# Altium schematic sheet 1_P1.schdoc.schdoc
size 309 x 223 mm; Symbol: Sheet-Symbol_A4; Device: Sheet-Symbol_A4; Company: Sai Automations; Drawed: EasyEDA Pro; Reviewed: EasyEDA Pro; Version: V0.1; Page Size: A4; @Project Name: SHA-PCB V1.1; @Page Count: 2; @Update Date: 2024-07-24; @Create Date: 2023-12-23; @Schematic Name: Schematic1; Part Number: JLCPCB-002; @Page No: 1; @Page Name: P1
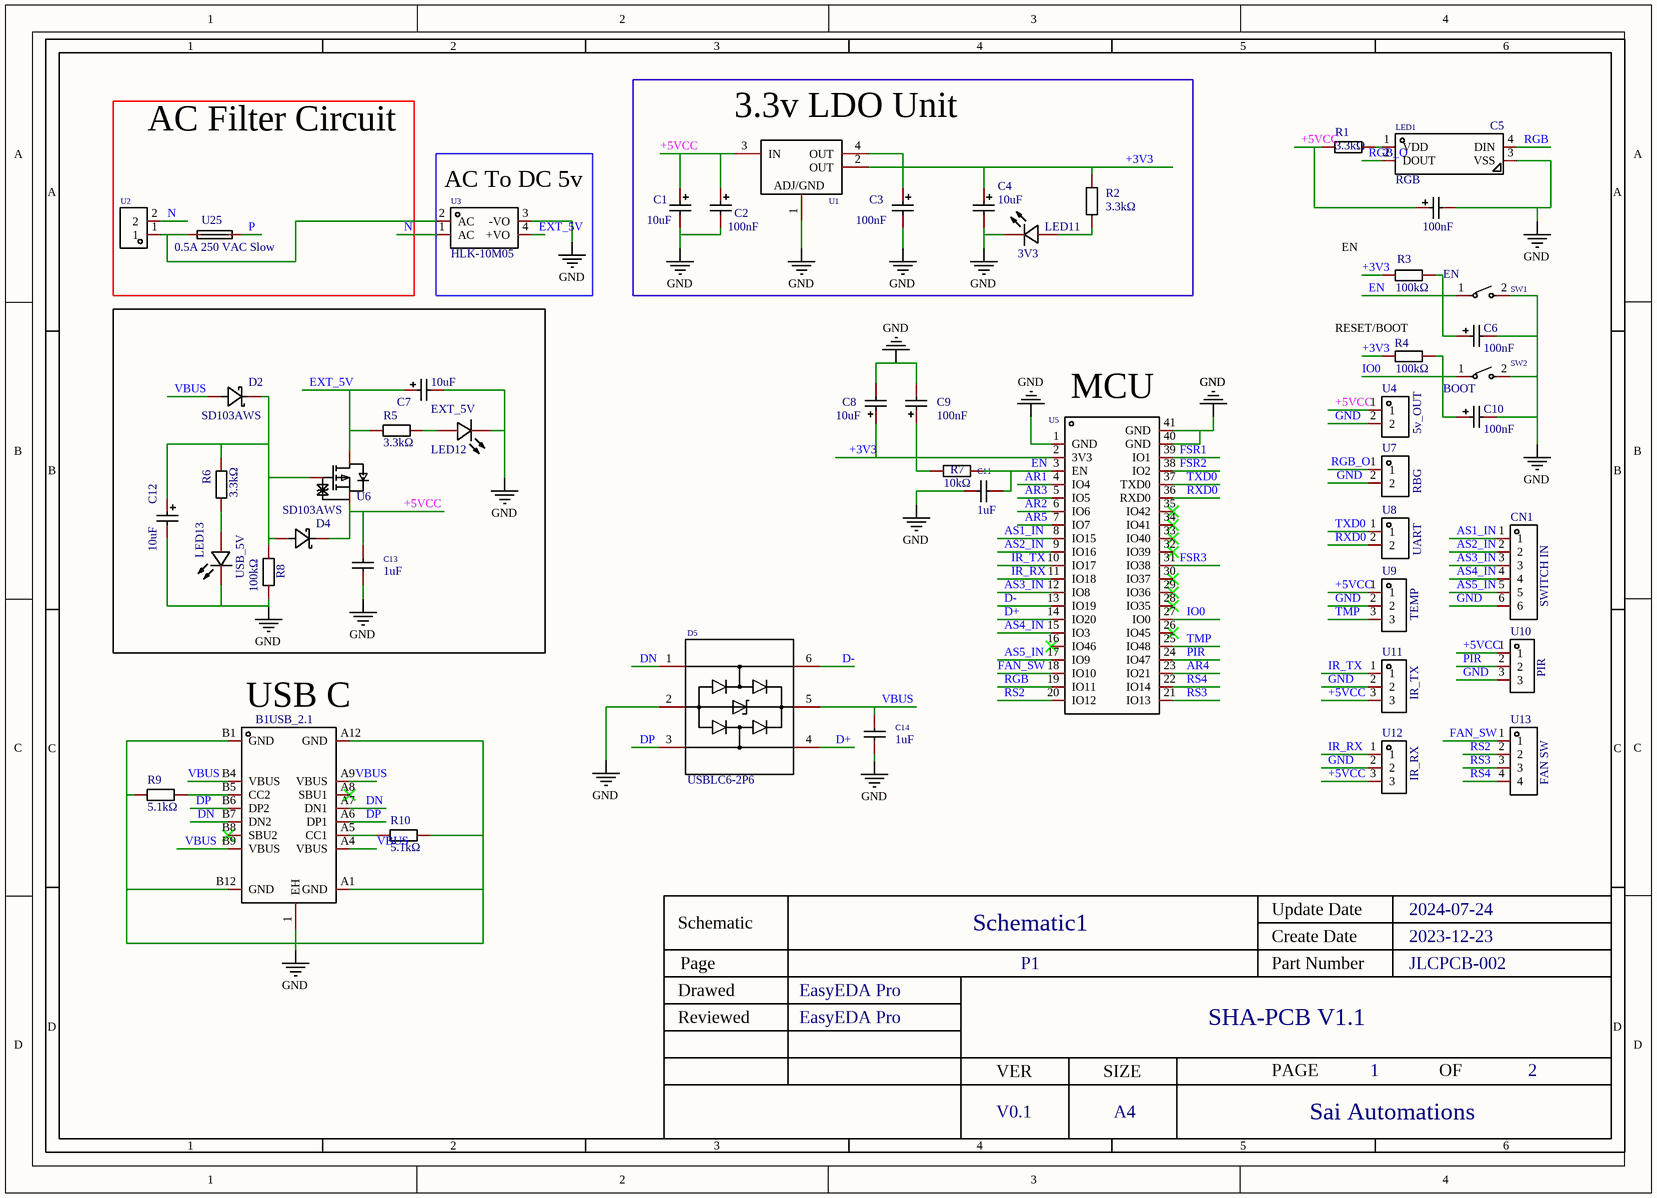
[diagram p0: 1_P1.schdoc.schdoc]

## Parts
B1  USB_2.1  [TYPE-C-SMD_SBC-160S1A-20-S412]
C1  10uF  [CASE-A_3216]
C2  100nF  [CASE-A_3216]
C3  100nF  [CASE-A_3216]
C4  10uF  [CASE-A_3216]
C5  100nF  [CASE-A_3216]
C6  100nF  [CASE-A_3216]
C7  10uF  [CASE-A_3216]
C8  10uF  [CASE-B_3528]
C9  100nF  [CASE-A_3216]
C10  100nF  [CASE-A_3216]
C11  1uF  [C0402]
C12  10uF  [CASE-A_3216]
C13  1uF  [C0402]
C14  1uF  [C0402]
CN1  SWITCH IN  [CONN-TH_B6B-PH-K-S-GW]
D2  SD103AWS  [SOD-323_L1.8-W1.3-LS2.5-FD]
D4  SD103AWS  [SOD-323_L1.8-W1.3-LS2.5-FD]
D5  USBLC6-2P6  [SOT-666-6_L1.6-W1.2-P0.50-LS1.6-BR]
LED1  RGB  [LED-SMD_4P-L5.0-W5.0-BL_TC5050RGB]
LED11  3V3  [LED0805-R-RD]
LED12  EXT_5V  [LED0805-R-RD]
LED13  USB_5V  [LED0805-R-RD]
R1  3.3kΩ  [R0402]
R2  3.3kΩ  [R0402]
R3  100kΩ  [R0402]
R4  100kΩ  [R0402]
R5  3.3kΩ  [R0402]
R6  3.3kΩ  [R0402]
R7  10kΩ  [R0402]
R8  100kΩ  [R0402]
R9  5.1kΩ  [R0402]
R10  5.1kΩ  [R0402]
SW1  EN  [SW-SMD_L3.9-W3.0-P4.45]
SW2  BOOT  [SW-SMD_L3.9-W3.0-P4.45]
U1  AMS1117-3.3  [SOT-223-3_L6.4-W3.5-P2.30-LS7.0-BR]  (value not drawn)
U2  XY126V-5.0-2P  [CONN-TH_XY126V-5.0-2P]  (value not drawn)
U3  HLK-10M05  [PWRM-TH_HLK-10M05]
U4  5v_OUT  [CONN-TH_2P-P2.00_2B-PH-KL]
U5  ESP32-S3-WROOM-1-N4R8  [WIRELM-SMD_ESP32-S3-WROOM-1]  (value not drawn)
U6  CJ3139KDW-ES  [SOT-323-3_L2.1-W1.3-P1.30-LS2.3-BR]  (value not drawn)
U7  RBG  [CONN-TH_2P-P2.00_2B-PH-KL]
U8  UART  [CONN-TH_2P-P2.00_2B-PH-KL]
U9  TEMP  [3 PIN JST PH]
U10  PIR  [3 PIN JST PH]
U11  IR_TX  [3 PIN JST PH]
U12  IR_RX  [3 PIN JST PH]
U13  FAN SW  [JST 4PIN]
U25  0.5A 250 VAC Slow  [TH_2P-BLX-A]

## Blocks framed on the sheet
3.3v LDO Unit: C1-C4 LED11 R2 U1
AC Filter Circuit: U2 U25
AC To DC 5v: U3

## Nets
GND: B1.1(EH) B1.A1(GND) B1.A12(GND) B1.B1(GND) B1.B12(GND) C1.2 C2.2 C3.2 C4.2 C5.2 C6.2 C7.2 C8.2 C9.2 C10.2 C11.2 C12.2 C13.2 C14.2 CN1.6 D5.2(GND) LED1.3(VSS) LED11.2(-) LED12.2(-) LED13.2(-) R8.1 R9.1 R10.2 SW1.2 SW2.2 U1.1(ADJ/GND) U3.3(-VO) U4.2 U5.1(GND) U5.40(GND) U5.41(GND) U7.2 U9.2 U10.3 U11.2 U12.2
+3V3: C3.1 C4.1 C8.1 C9.1 R2.2 R3.1 R4.2 R7.2 U1.2(OUT) U1.4(OUT) U5.2(3V3)
+5VCC: C1.1 C2.1 C5.1 C13.1 D4.2(K) R1.1 U1.3(IN) U4.1 U6.2(S) U9.1 U10.1 U11.3 U12.3
AR1: U5.4(IO4)
AR2: U5.6(IO6)
AR3: U5.5(IO5)
AR4: U5.23(IO21)
AR5: U5.7(IO7)
AS1_IN: CN1.1 U5.8(IO15)
AS2_IN: CN1.2 U5.9(IO16)
AS3_IN: CN1.3 U5.12(IO8)
AS4_IN: CN1.4 U5.15(IO3)
AS5_IN: CN1.5 U5.17(IO9)
D+: D5.4(I/O2) U5.14(IO20)
D-: D5.6(I/O1) U5.13(IO19)
DN: B1.A7(DN1) B1.B7(DN2) D5.1(I/O1)
DP: B1.A6(DP1) B1.B6(DP2) D5.3(I/O2)
EN: C6.1 C11.1 R3.2 R7.1 SW1.1 U5.3(EN)
EXT_5V: C7.1 R5.1 U3.4(+VO) U6.3(D)
FAN_SW: U5.18(IO10) U13.1
FSR1: U5.39(IO1)
FSR2: U5.38(IO2)
FSR3: U5.31(IO38)
IO0: C10.1 R4.1 SW2.1 U5.27(IO0)
IR_RX: U5.11(IO18) U12.1
IR_TX: U5.10(IO17) U11.1
N: U2.2 U3.1(AC)
P: U25.2
PIR: U5.24(IO47) U10.2
RGB: LED1.4(DIN) U5.19(IO11)
RGB_O: LED1.2(DOUT) U7.1
RS2: U5.20(IO12) U13.2
RS3: U5.21(IO13) U13.3
RS4: U5.22(IO14) U13.4
RXD0: U5.36(RXD0) U8.2
TMP: U5.25(IO48) U9.3
TXD0: U5.37(TXD0) U8.1
VBUS: B1.A4(VBUS) B1.A9(VBUS) B1.B4(VBUS) B1.B9(VBUS) C14.1 D2.1(A) D5.5(VBUS)
NetB1_A5: B1.A5(CC1) R10.1
NetB1_B5: B1.B5(CC2) R9.2
NetC12_1: C12.1 D2.2(K) D4.1(A) R6.1 R8.2 U6.1(G)
NetLED1_1: LED1.1(VDD) R1.2
NetLED11_1: LED11.1(+) R2.1
NetLED12_1: LED12.1(+) R5.2
NetLED13_1: LED13.1(+) R6.2
NetU2_1: U2.1 U3.2(AC) U25.1

Not connected (* = marked no-connect by the designer): B1 A8(SBU1)* B8(SBU2)*; U5 16(IO46)* 26(IO45)* 28(IO35)* 29(IO36)* 30(IO37)* 32(IO39)* 33(IO40)* 34(IO41)* 35(IO42)*

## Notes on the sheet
- (near R3) EN
- (near R4) RESET/BOOT
- (near U5) MCU
- (near B1) USB C

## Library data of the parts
B1 = USB4105-GF-A: Add into BOM: yes
C1 C4 C7 C12 = TAJA106K010RNJ: Manufacturer: Kyocera AVX; Add into BOM: yes; Tolerance: ±10%; Equivalent Series Resistance(ESR): 3Ω@100kHz; Description: Capacitance: Tolerance:±10% Tolerance:±10% Rated Voltage: Equivalent Series Resistance(ESR):3Ω@100kHz Operating Temperature:-55℃~+125℃ Operating Temperature:-55℃~+125℃
C2 C3 C5 C6 C9 C10 = TAJA104K035RNJ: Manufacturer: Kyocera AVX; Add into BOM: yes; Tolerance: ±10%; Equivalent Series Resistance(ESR): 24Ω@100kHz; Description: Capacitance: Tolerance:±10% Tolerance:±10% Rated Voltage: Equivalent Series Resistance(ESR):24Ω@100kHz Operating Temperature:-55℃~+125℃ Operating Temperature:-55℃~+125℃
C8 = TAJB226K016RNJ: Manufacturer: Kyocera AVX; Add into BOM: yes; Tolerance: ±10%; Equivalent Series Resistance(ESR): 2.3Ω@100kHz; Description: Capacitance: Tolerance:±10% Tolerance:±10% Rated Voltage: Equivalent Series Resistance(ESR):2.3Ω@100kHz Operating Temperature:-55℃~+125℃ Operating Temperature:-55℃~+125℃
C11 C13 C14 = CL05A105KP5NNNC: Manufacturer: SAMSUNG(三星); Add into BOM: yes; Tolerance: ±10%; Description: Capacitance: Tolerance:±10% Tolerance:±10% Voltage Rated: Temperature Coefficient:
CN1 = B6B-PH-K-S-GW: Manufacturer: JST; Add into BOM: yes; Pins Structure: 1x6P; Pitch: 2mm; Reference Series: PH; Number of PINs Per Row: 6; Current Rating (Max): 2A; Rated Voltage (Max): 100V; Plastic Material: PA66; Flame Retardant Rating: UL94V-0; Supplementary Features: 打K脚; Z-Height of the Board: 6mm; X-Length of Bottom Edge on Board (Spacing Line): 13.9mm; Y-Width of Bottom Edge on Board: 4.5mm; Description: Pins Structure:1x6P Pitch:2mm Mounting Style:Straight Reference Series:PH Number of Pins:6P Number of Rows:1 Number of PINs Per Row:6 Row Spacing:- Current Rating (Max):2A Contact Material:Brass Contact Plating:Tin Operating Temperature Range:-25℃~+85℃ Op
D2 D4 = SD103AWS_C777800: Manufacturer: HT(金誉); Add into BOM: yes
D5 = USBLC6-2P6_C15999: Manufacturer: ST(意法半导体); Add into BOM: yes; polarity: Unidirectional; Reverse Stand-Off Voltage (Vrwm): 5.25V; Maximum Clamping Voltage: 17V; Peak Pulse Current (Ipp)@10/1000us: 5A; Breakdown Voltage: 6V; Number of Lines: Dual; Type: ESD; Description: polarity:Unidirectional Reverse Stand-Off Voltage (Vrwm):5.25V Maximum Clamping Voltage:17V Peak Pulse Current (Ipp)@10/1000us:5A Breakdown Voltage:6V Number of Lines:Dual Type:ESD
LED1 = WS2812B-B/W: Manufacturer: worldsemi; Add into BOM: yes; Description: Emitted Color:RGB
LED11-LED13 = KT-0805Y: Manufacturer: KENTO; Symbol: 17-21SUYC/TR8; Add into BOM: yes; Emitted Color: Yellow; Description: Emitted Color:Yellow Diode Configuration:- Forward Current:- Power Dissipation:- Lens Color:- Dominant Wavelength:- Dominant Wavelength:- Peak Wavelength:- Color Temperature:- Color Temperature:- Viewing Angle:- Mounting Sytle:- Operating Temperature:- Op
R1 R2 R5 R6 = RC0402FR-073K3L: Manufacturer: YAGEO(国巨); Add into BOM: yes; Tolerance: ±1%; Temperature Coefficient: ±100ppm/℃; Description: Type:Thick Film Resistors Resistance: Tolerance:±1% Tolerance:±1% Power(Watts): Overload Voltage (Max): Temperature Coefficient:±100ppm/℃ Temperature Coefficient:±100ppm/℃ Operating Temperature Range:-55℃~+155℃ Operating Temperature Range:-55℃~+155℃
R3 R4 R8 = RC0402FR-07100KL: Manufacturer: YAGEO(国巨); Add into BOM: yes; Tolerance: ±1%; Temperature Coefficient: ±100ppm/℃; Description: Type:Thick Film Resistors Resistance: Tolerance:±1% Tolerance:±1% Power(Watts): Overload Voltage (Max): Temperature Coefficient:±100ppm/℃ Temperature Coefficient:±100ppm/℃ Operating Temperature Range:-55℃~+155℃ Operating Temperature Range:-55℃~+155℃
R7 = RC0402FR-0710KL: Manufacturer: YAGEO(国巨); Add into BOM: yes; Tolerance: ±1%; Temperature Coefficient: ±100ppm/℃; Description: Type:Thick Film Resistors Resistance: Tolerance:±1% Tolerance:±1% Power(Watts): Temperature Coefficient:±100ppm/℃ Temperature Coefficient:±100ppm/℃ Overload Voltage (Max): Operating Temperature Range:-55℃~+155℃ Operating Temperature Range:-55℃~+155℃
R9 R10 = RC0402FR-075K1L: Manufacturer: YAGEO(国巨); Add into BOM: yes; Tolerance: ±1%; Temperature Coefficient: ±100ppm/℃; Description: Type:Thick Film Resistors Resistance: Tolerance:±1% Tolerance:±1% Power(Watts): Overload Voltage (Max): Temperature Coefficient:±100ppm/℃ Temperature Coefficient:±100ppm/℃ Operating Temperature Range:-55℃~+155℃ Operating Temperature Range:-55℃~+155℃
SW1 SW2 = TS-1088R-02526: Manufacturer: XUNPU(讯普); Add into BOM: yes; Circuit: SPST; Actuator Style: Round Button; Switch Length: 3.9mm; Switch Width: 2.93mm; Switch Height: 2.5mm; Contact Current: 50mA; Voltage Rating (DC): 12V; Description: Circuit:SPST Actuator Style:Round Button Mounting Style:Brick nogging Switch Length:3.9mm Switch Width:2.93mm Switch Height:2.5mm Contact Current:50mA Voltage Rating (DC):12V With Lamp:- Mechanical Life:-
U1 = AMS1117-3.3: Manufacturer: 国芯佳品; Symbol: AMS1117-3.3_C2992570; Add into BOM: yes
U2 = XY126V-5.0-2P: Manufacturer: XINLAIYA(新莱亚); Add into BOM: yes; Structure: 1x2P; Pitch: 5mm; Current Rating (Max): 10A; Voltage Rating (Max): 300V; Wire Gauge - AWG: 14~26; Wire Gauge - mm2: 2.5; Number of PINs Per Row: 2; Description: Structure:1x2P Pitch:5mm Color:Green Mounting Style:Straight Current Rating (Max):10A Voltage Rating (Max):300V Number of Pins:2P Number of Rows:1 Wire Gauge - AWG:14~26 Wire Gauge - AWG:14~26 Wire Gauge - mm2:2.5 Wire Gauge - mm2:2.5 Number of PINs Per R
U3 = HLK-10M05: Manufacturer: HI-LINK(海凌科); Add into BOM: yes; Conversion Type: AC-DC; Function: 降压型; Input Voltage(AC): 90VAC~265VAC; Input Voltage(DC): 120V~350V; Output Voltage: 5V; Output Current (Max): 2A; Output Power: 10W; Isolated Or Voltage Regulation: 隔离稳压; Output Channel: 1; Insulated Voltage: 3kV@AC; Conversion Efficiency: 80%; Description: Conversion Type:AC-DC Function:降压型 Input Voltage(AC):90VAC~265VAC Input Voltage(AC):90VAC~265VAC Input Voltage(DC):120V~350V Input Voltage(DC):120V~350V Output Voltage:5V Output Voltage:5V Output Current (Max):2A Output Current (Max):2A Output Power:10W I
U4 U7 U8 = B2B-PH-KL(LF)(SN): Manufacturer: JST; Add into BOM: yes; Pins Structure: 1x2P; Pitch: 2mm; Reference Series: PH; Number of PINs Per Row: 2; Current Rating (Max): 2A; Rated Voltage (Max): 100V; Plastic Material: PA66; Flame Retardant Rating: UL94V-0; Supplementary Features: 打K脚; Z-Height of the Board: 6mm; X-Length of Bottom Edge on Board (Spacing Line): 5.9mm; Y-Width of Bottom Edge on Board: 4.5mm; Description: Pins Structure:1x2P Pitch:2mm Mounting Style:Straight Reference Series:PH Number of Pins:2P Number of Rows:1 Number of PINs Per Row:2 Row Spacing:- Current Rating (Max):2A Contact Material:Copper Alloy Contact Plating:Tin Operating Temperature Range:-25℃~
U5 = ESP32-S3-WROOM-1-N4R8: Manufacturer: ESPRESSIF(乐鑫); Add into BOM: yes
U6 = CJ3139KDW-ES: Manufacturer: ElecSuper(静芯微); Add into BOM: yes; Continuous Drain Current (Id): 0.5A; Power Dissipation (Pd): 0.15W; Drain Source On Resistance (RDS(on)@Vgs,Id): 580mΩ; Gate Threshold Voltage (Vgs(th)@Id): 0.62V; Total Gate Charge (Qg@Vgs): 1.25nC; Input Capacitance (Ciss@Vds): 71pF; Reverse Transfer Capacitance (Crss@Vds): 15pF; Description: Drain Source Voltage (Vdss): Continuous Drain Current (Id):0.5A Power Dissipation (Pd):0.15W Drain Source On Resistance (RDS(on)@Vgs,Id):580mΩ Gate Threshold Voltage (Vgs(th)@Id):0.62V Total Gate Charge (Qg@Vgs):1.25nC Input Capacitance (Ciss@Vds):71pF Re
U9-U12 = B4B-PH-K-S-GW: Manufacturer: JST; Add into BOM: yes; Pins Structure: 1x4P; Pitch: 2mm; Reference Series: PH; Number of PINs Per Row: 4; Current Rating (Max): 2A; Rated Voltage (Max): 100V; Plastic Material: PA66; Flame Retardant Rating: UL94V-0; Supplementary Features: 打K脚; Z-Height of the Board: 6mm; X-Length of Bottom Edge on Board (Spacing Line): 9.9mm; Y-Width of Bottom Edge on Board: 4.5mm; Description: Pins Structure:1x4P Pitch:2mm Mounting Style:Straight Reference Series:PH Number of Pins:4P Number of Rows:1 Number of PINs Per Row:4 Row Spacing:- Current Rating (Max):2A Contact Material:Brass Contact Plating:Tin Operating Temperature Range:-25℃~+85℃ Op
U13 = B4B-PH-KL(LF)(SN): Manufacturer: JST; Add into BOM: yes; Pins Structure: 1x4P; Pitch: 2mm; Reference Series: PH; Number of PINs Per Row: 4; Current Rating (Max): 2A; Rated Voltage (Max): 100V; Plastic Material: PA66; Flame Retardant Rating: UL94V-0; Supplementary Features: 打K脚; Z-Height of the Board: 6mm; X-Length of Bottom Edge on Board (Spacing Line): 9.9mm; Y-Width of Bottom Edge on Board: 4.5mm; Description: Pins Structure:1x4P Pitch:2mm Mounting Style:Straight Reference Series:PH Number of Pins:4P Number of Rows:1 Number of PINs Per Row:4 Row Spacing:- Current Rating (Max):2A Contact Material:Copper Alloy Contact Plating:Tin Operating Temperature Range:-25℃~
U25 = BLX-A保险座: Add into BOM: yes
